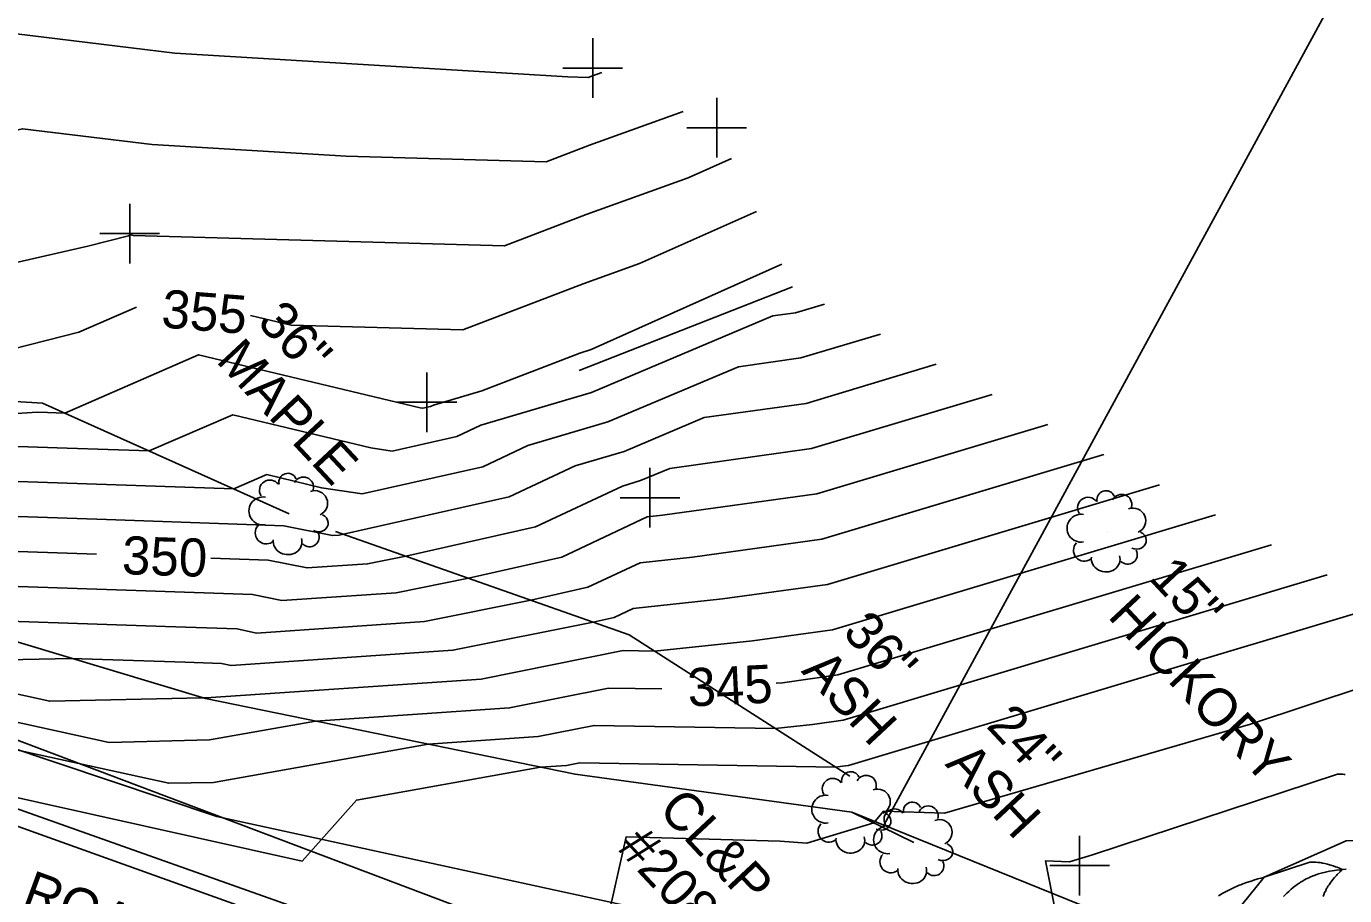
# Model space of a CAD drawing. Extents: x 487096 to 489566, y 221939 to 224454.
# Drawn here: x 488109.6 to 488220.2, y 223699.1 to 223772 of the extents above; entities that cross this region are included whole.
import ezdxf

# ---------------------------------------------------------------- set-up
doc = ezdxf.new("R2010")
doc.units = 0
for name, color, linetype in [('SV_BKLN_EARTH_TOP', 7, 'Continuous'), ('SV_FENC_FENCES', 7, 'Continuous'), ('SV_ROAD_BITRD', 7, 'Continuous'), ('SV_ROWL_HWYLOC', 7, 'Continuous'), ('SV_ROWL_PROP', 7, 'Continuous'), ('SV_ROWL_ROWL_TX', 7, 'Continuous'), ('SV_SURF_INDEX_CONTOUR', 7, 'Continuous'), ('SV_SURF_INTER_CONTOUR', 7, 'Continuous'), ('SV_SURF_SPOT', 7, 'Continuous'), ('SV_TRAF_PVMTL', 7, 'Continuous'), ('SV_TREE_TREELN', 7, 'Continuous'), ('SV_TREE_TREEVEG', 7, 'Continuous'), ('SV_TREE_TREEVEG_TX', 7, 'Continuous'), ('SV_UTOH_OVERHEAD_LINES', 7, 'Continuous'), ('SV_UTOH_UTOH_TX', 7, 'Continuous'), ('SV_WALL_STONE_WALL', 7, 'Continuous'), ('SV_WATR_INWETF', 7, 'Continuous'), ('SV_WATR_STREAM', 7, 'Continuous')]:
    doc.layers.add(name, color=color, linetype=linetype)

msp = doc.modelspace()

# ---------------------------------------------------------------- linework, layer by layer
at = {"layer": 'SV_BKLN_EARTH_TOP'}
for points in [[(488041.14, 223750.63), (488051.84, 223755.29), (488071.96, 223735.45), (488100.92, 223722.74), (488124.66, 223715.6), (488155.68, 223709.25)], [(488156.02, 223743.16), (488173.91, 223750.18)]]:
    msp.add_lwpolyline(points, dxfattribs=at)
at = {"layer": 'SV_FENC_FENCES'}
msp.add_lwpolyline([(487982.51, 223759.36), (488009.69, 223754.74), (488041.14, 223750.63), (488071.96, 223735.45), (488100.92, 223722.74), (488124.66, 223715.6), (488155.68, 223709.25), (488178.9, 223706.07), (488184.09, 223703.51)], dxfattribs=at)
at = {"layer": 'SV_ROAD_BITRD'}
msp.add_lwpolyline([(488195.32, 223676.23), (488156.88, 223689.32), (488086.86, 223714.16), (488030.43, 223734.89), (488029.27, 223735.37), (487991.62, 223750.14), (487935.77, 223771.81)], dxfattribs=at)
at = {"layer": 'SV_ROWL_HWYLOC'}
msp.add_lwpolyline([(487756.92, 223854.03), (487819.74, 223823.93), (487982.51, 223759.36), (488009.69, 223754.74), (488041.14, 223750.63), (488071.96, 223735.45), (488100.92, 223722.74), (488124.66, 223715.6), (488155.68, 223709.25), (488178.9, 223706.07), (488296.16, 223658.56), (488379.4, 223617.17), (488410.15, 223595.68), (488443.8, 223549.21), (488472.24, 223469.86), (488477.06, 223418.16), (488475.62, 223352.08), (488474.08, 223317.48), (488463.17, 223231.25), (488461.58, 223189.46)], dxfattribs=at)
at = {"layer": 'SV_ROWL_PROP'}
msp.add_line((488181.59, 223704.98), (488227.81, 223790.02), dxfattribs=at)
at = {"layer": 'SV_SURF_INDEX_CONTOUR'}
for points in [[(488128.45, 223747.77), (488131.84, 223746.96), (488146.26, 223746.56), (488156.35, 223750.41), (488161.09, 223752.12), (488170.9, 223756.5)], [(488037.34, 223752.77), (488037.74, 223752.37), (488038.25, 223751.01), (488040.43, 223749.72), (488040.51, 223749.7), (488041.1, 223749.58), (488048.91, 223750.37), (488064.4, 223742.91), (488076.16, 223740.46), (488080.11, 223740.49), (488094.61, 223741.41), (488114.05, 223746.37), (488118.87, 223748.47)], [(488032.68, 223745.08), (488035.52, 223743.4), (488036.1, 223743.22), (488040.76, 223742.28), (488044.31, 223742.64), (488058.56, 223735.77), (488076.6, 223728.82), (488077.44, 223728.86), (488090.01, 223727.53), (488095.27, 223727.56), (488103.98, 223728.12), (488115.53, 223727.73)], [(488125.12, 223727.4), (488129.92, 223727.23), (488133.19, 223726.57), (488138.26, 223726.91), (488141.48, 223727.56), (488152.35, 223730.01), (488159.66, 223733.45), (488161.16, 223733.9), (488163.62, 223734.93), (488175.5, 223736.59), (488190.66, 223741.14)], [(488214.09, 223728.51), (488177.73, 223717.59), (488173.08, 223716.94), (488172.55, 223716.89)], [(488162.96, 223716.42), (488158.49, 223716.49), (488150.18, 223714.82), (488133.89, 223713.71), (488124.99, 223712.13), (488116.59, 223711.93), (488092.03, 223717.31), (488085.77, 223718.14), (488084.12, 223718.08), (488077.99, 223720.44)], [(488218.43, 223698.98), (488218.52, 223699.22), (488218.53, 223699.23), (488218.58, 223699.37), (488218.62, 223699.42), (488218.72, 223699.66), (488218.76, 223699.71), (488218.8, 223699.76), (488218.84, 223699.86), (488218.93, 223699.96), (488219.02, 223700.12), (488219.07, 223700.18), (488219.19, 223700.32), (488219.26, 223700.43), (488219.4, 223700.59), (488219.44, 223700.64), (488219.55, 223700.76), (488219.6, 223700.83), (488219.85, 223701.07), (488219.86, 223701.09), (488220.02, 223701.23), (488220.02, 223701.23), (488220.04, 223701.26), (488220.02, 223701.26), (488219.87, 223701.33), (488219.6, 223701.44), (488219.46, 223701.49), (488219.27, 223701.56), (488219.07, 223701.62), (488218.98, 223701.65), (488218.79, 223701.7), (488218.7, 223701.73), (488218.57, 223701.76), (488218.39, 223701.8), (488218.3, 223701.81), (488218.18, 223701.83), (488217.99, 223701.85), (488217.82, 223701.87), (488217.74, 223701.87), (488217.62, 223701.87), (488217.51, 223701.87), (488217.45, 223701.87), (488217.33, 223701.86), (488213.5, 223700.6), (488213.38, 223700.57), (488213.21, 223700.52), (488212.95, 223700.46), (488212.79, 223700.41), (488212.68, 223700.38), (488212.47, 223700.31), (488212.31, 223700.26), (488212, 223700.16), (488211.71, 223700.05), (488211.52, 223699.98), (488211.4, 223699.93), (488211.16, 223699.82), (488211.02, 223699.76), (488210.76, 223699.64), (488210.51, 223699.52), (488210.35, 223699.43), (488210.24, 223699.38), (488210.03, 223699.26), (488209.8, 223699.13), (488209.65, 223699.04)]]:
    msp.add_lwpolyline(points, dxfattribs=at)
at = {"layer": 'SV_SURF_INTER_CONTOUR'}
for points in [[(487924.69, 223852.33), (487977.96, 223831.88), (487978.79, 223831), (487981.69, 223830.6), (487983.88, 223829.55), (488033.44, 223796.8), (488033.51, 223796.69), (488033.55, 223796.51), (488045.78, 223756.98), (488046.69, 223753.05), (488050.75, 223753.46), (488056.51, 223750.69), (488064.5, 223749.03), (488079.62, 223756.68), (488109.3, 223763.45), (488120.18, 223762.12), (488136.47, 223761.14), (488153.26, 223760.68), (488156.87, 223762.06), (488164.73, 223764.89)], [(487925.08, 223846.87), (487972.43, 223828.69), (487974.22, 223826.8), (487980.52, 223825.94), (487985.26, 223823.65), (488029.19, 223794.62), (488030.01, 223793.27), (488030.55, 223791.08), (488040.65, 223758.4), (488042.35, 223751.16), (488049.83, 223751.92), (488060.45, 223746.8), (488075.2, 223743.73), (488078.17, 223745.23), (488114.8, 223753.59), (488118.21, 223754.46), (488118.37, 223754.53), (488118.61, 223754.47), (488149.76, 223753.62), (488156.61, 223756.24), (488165.17, 223759.32), (488168.79, 223760.94)], [(488157.93, 223768.17), (488157.13, 223767.88), (488156.77, 223767.74), (488155.06, 223767.79), (488122.09, 223769.78), (488100.08, 223772.47), (488081.07, 223768.13), (488053.8, 223754.32), (488052.56, 223754.58), (488051.67, 223755.01), (488051.04, 223754.94), (488050.9, 223755.55), (488048.82, 223762.28), (488050.68, 223794.13), (487990.14, 223831.22)], [(488218.77, 223725.98), (488178.17, 223713.79), (488175.6, 223713.43), (488172.46, 223713.1), (488157.27, 223713.35), (488152.57, 223712.41), (488143.34, 223711.77), (488125.33, 223708.57), (488121.59, 223708.49), (488089.19, 223715.58), (488086.37, 223715.95), (488085.63, 223715.93), (488072.54, 223720.97), (488032.36, 223735.14), (488030.82, 223735.46), (488029.62, 223735.82), (488027.6, 223737.02), (488024.43, 223738.33), (487992.98, 223750.21), (487991.95, 223751.33), (487987.72, 223754.08), (487959.79, 223762.49)], [(488173.01, 223752.07), (488157.01, 223744.92), (488156.08, 223744.59), (488147.86, 223741.45), (488143.79, 223740.24), (488143.54, 223740.13), (488142.89, 223739.98), (488142.67, 223740.02), (488124.09, 223744.47), (488112.86, 223739.57), (488111.42, 223739.62), (488110.56, 223739.65), (488083.14, 223737.9)], [(488176.6, 223748.73), (488174.16, 223748), (488172.26, 223747.73), (488157.05, 223741.3), (488147.76, 223738.55), (488145.74, 223737.6), (488140.34, 223736.38), (488138.53, 223736.66), (488126.95, 223739.44), (488119.95, 223736.39), (488113.07, 223736.63), (488108.92, 223736.77)], [(488107.27, 223733.88), (488114.72, 223733.63), (488127.04, 223733.2), (488129.81, 223734.41), (488134.39, 223733.31), (488137.8, 223732.78), (488147.94, 223735.07), (488151.72, 223736.85), (488158.42, 223738.83), (488169.38, 223743.46), (488174.61, 223744.2), (488181.29, 223746.2)], [(488185.97, 223743.67), (488175.06, 223740.39), (488166.5, 223739.2), (488159.79, 223736.36), (488155.69, 223735.15), (488150.15, 223732.54), (488136.24, 223729.4), (488135.88, 223729.33), (488135.31, 223729.29), (488131.23, 223730.12), (488116.37, 223730.64), (488105.63, 223731)], [(488102.34, 223725.23), (488119.67, 223724.65), (488128.61, 223724.34), (488131.07, 223723.84), (488140.65, 223724.49), (488146.72, 223725.71), (488154.55, 223727.48), (488161.71, 223730.85), (488163.02, 223730.99), (488175.95, 223732.79), (488195.34, 223738.62)], [(488200.03, 223736.09), (488176.39, 223728.99), (488165.53, 223727.48), (488161.13, 223727.01), (488156.75, 223724.95), (488151.96, 223723.87), (488143.03, 223722.08), (488128.95, 223721.11), (488127.31, 223721.45), (488121.32, 223721.66), (488102.42, 223722.29)], [(488204.71, 223733.56), (488176.84, 223725.19), (488168.05, 223723.97), (488160.56, 223723.18), (488158.95, 223722.42), (488157.19, 223722.03), (488145.42, 223719.66), (488126.83, 223718.39), (488126, 223718.56), (488122.97, 223718.66), (488113.41, 223718.98), (488106.6, 223718.83)], [(488209.4, 223731.03), (488177.28, 223721.39), (488170.57, 223720.45), (488162.35, 223719.59), (488159.71, 223719.63), (488147.8, 223717.24), (488124.71, 223715.66), (488124.69, 223715.67), (488124.62, 223715.67), (488124.4, 223715.68), (488111.6, 223715.38), (488094.86, 223719.04)], [(488223.46, 223723.45), (488178.62, 223709.99), (488178.12, 223709.92), (488177.51, 223709.86), (488156.06, 223710.21), (488154.95, 223709.99), (488152.78, 223709.84), (488137.33, 223707.09), (488132.77, 223701.96), (488101.76, 223708.87)], [(488221.97, 223716.64), (488212.33, 223713.46), (488186.67, 223705.99), (488181.54, 223706.15), (488180.73, 223705.16), (488175.11, 223703.46), (488172.88, 223703.64), (488159.96, 223704.01), (488158.36, 223696.9), (488158.3, 223691.66), (488159.24, 223691.37), (488180.42, 223681.3), (488180.55, 223680.64), (488182.51, 223678.74), (488182.68, 223675.18), (488212.07, 223664.63), (488242.33, 223657.26)], [(488220.28, 223709.22), (488220.2, 223709.23), (488220.08, 223709.25), (488219.97, 223709.25), (488219.92, 223709.26), (488219.84, 223709.26), (488219.76, 223709.25), (488219.73, 223709.25), (488219.65, 223709.25), (488199.08, 223702.48), (488197.15, 223701.91), (488195.14, 223701.98), (488197.11, 223691.98)]]:
    msp.add_lwpolyline(points, dxfattribs=at)
at = {"layer": 'SV_SURF_SPOT'}
for p, q in [((488157.16, 223766.04), (488157.16, 223771.04)), ((488154.66, 223768.54), (488159.66, 223768.54)), ((488157.16, 223768.54), (488157.16, 223768.54)), ((488167.56, 223761.03), (488167.56, 223766.03)), ((488165.05, 223763.53), (488170.06, 223763.53)), ((488167.56, 223763.53), (488167.56, 223763.53)), ((488118.31, 223752.14), (488118.31, 223757.14)), ((488115.81, 223754.64), (488120.81, 223754.64)), ((488118.31, 223754.64), (488118.31, 223754.64)), ((488143.24, 223737.98), (488143.24, 223742.98)), ((488140.74, 223740.48), (488145.74, 223740.48)), ((488143.24, 223740.48), (488143.24, 223740.48)), ((488161.95, 223729.97), (488161.95, 223734.97)), ((488159.45, 223732.47), (488164.45, 223732.47)), ((488161.95, 223732.47), (488161.95, 223732.47)), ((488198, 223699.08), (488198, 223704.08)), ((488195.5, 223701.58), (488200.5, 223701.58)), ((488198, 223701.58), (488198, 223701.58))]:
    msp.add_line(p, q, dxfattribs=at)
at = {"layer": 'SV_TRAF_PVMTL'}
msp.add_lwpolyline([(488242.49, 223657.77), (488197.68, 223673.45), (488156.59, 223687.78), (488086.23, 223713.02)], dxfattribs=at)
at = {"layer": 'SV_TREE_TREELN'}
msp.add_lwpolyline([(487982.51, 223759.36), (488004.13, 223750.78), (488040.48, 223736.21), (488085.49, 223719.17), (488125.61, 223705.71), (488165.7, 223696.97), (488203.95, 223688.95)], dxfattribs=at)
at = {"layer": 'SV_TREE_TREEVEG'}
for p, q in [((488131.68, 223731.12), (488131.68, 223731.12)), ((488200.32, 223729.66), (488200.32, 223729.66)), ((488178.9, 223706.07), (488178.9, 223706.07)), ((488184.09, 223703.51), (488184.09, 223703.51))]:
    msp.add_line(p, q, dxfattribs=at)
for centre, radius, start, end in [((488130.07, 223733.08), 0.874, 35.9933, 211.459), ((488131.57, 223733.77), 0.75, 23.2911, 192.3579), ((488132.89, 223733.35), 0.85, 345.5308, 152.7093), ((488133.85, 223732), 1.06, 294.1859, 111.1082), ((488200.21, 223732.31), 0.75, 23.2911, 192.3579), ((488201.53, 223731.9), 0.85, 345.5308, 152.7093), ((488129.48, 223731.36), 1.17, 79.3292, 279.9889), ((488198.71, 223731.63), 0.874, 35.9933, 211.459), ((488202.49, 223730.54), 1.06, 294.1859, 111.1082), ((488198.12, 223729.91), 1.17, 79.3292, 279.9889), ((488129.76, 223729.51), 0.922, 137.0157, 304.5501), ((488198.41, 223728.06), 0.922, 137.0157, 304.5501), ((488178.79, 223708.72), 0.75, 23.2911, 192.3579), ((488177.29, 223708.03), 0.874, 35.9933, 211.459), ((488180.1, 223708.31), 0.85, 345.5308, 152.7093), ((488176.7, 223706.32), 1.17, 79.3292, 279.9889), ((488181.06, 223706.95), 1.06, 294.1859, 111.1082), ((488182.47, 223705.47), 0.874, 35.9933, 211.459), ((488183.97, 223706.16), 0.75, 23.2911, 192.3579), ((488185.29, 223705.74), 0.85, 345.5308, 152.7093), ((488176.98, 223704.47), 0.922, 137.0157, 304.5501), ((488186.25, 223704.39), 1.06, 294.1859, 111.1082), ((488181.89, 223703.75), 1.17, 79.3292, 279.9889), ((488182.17, 223701.9), 0.922, 137.0157, 304.5501)]:
    msp.add_arc(centre, radius, start, end, dxfattribs=at)
for centre, major_axis, ratio, start_param, end_param in [((488134.14, 223730.35), (0.822, -0.013), 0.901056, 4.216583, 7.444153), ((488133.4, 223729.15), (0.08, -0.798), 0.999752, 5.391582, 8.241319), ((488202.78, 223728.89), (0.822, -0.013), 0.901056, 4.216583, 7.444153), ((488131.55, 223728.78), (-1.2, 0.16), 0.902156, 0, 3.5401), ((488200.19, 223727.33), (-1.2, 0.16), 0.902156, 0, 3.5401), ((488202.04, 223727.69), (0.08, -0.798), 0.999752, 5.391582, 8.241319), ((488181.35, 223705.3), (0.822, -0.013), 0.901056, 4.216583, 7.444153), ((488178.77, 223703.73), (-1.2, 0.16), 0.902156, 0, 3.5401), ((488180.62, 223704.1), (0.08, -0.798), 0.999752, 5.391582, 8.241319), ((488186.54, 223702.74), (0.822, -0.013), 0.901056, 4.216583, 7.444153), ((488185.81, 223701.54), (0.08, -0.798), 0.999752, 5.391582, 8.241319), ((488183.96, 223701.17), (-1.2, 0.16), 0.902156, 0, 3.5401)]:
    msp.add_ellipse(centre, major_axis=major_axis, ratio=ratio, start_param=start_param, end_param=end_param, dxfattribs=at)
at = {"layer": 'SV_UTOH_OVERHEAD_LINES'}
msp.add_lwpolyline([(488477.01, 222631.44), (488424.13, 222778.25), (488391.68, 223012.96), (488449.87, 223205.72), (488470, 223438.33), (488349.56, 223622.89), (488159.18, 223693.12), (487993.17, 223755.78), (487804.2, 223830.22), (487742.26, 223860.21)], dxfattribs=at)
at = {"layer": 'SV_WALL_STONE_WALL'}
for points in [[(487884.38, 223823.97), (487906, 223824.38), (487928.22, 223803.19), (487939.33, 223794.64), (487970.27, 223785.24), (487995.99, 223777.6), (488005.6, 223769.42), (488016.25, 223765.18), (488051.84, 223755.29), (488077.81, 223742.44), (488110.99, 223740.41), (488131.68, 223731.12)], [(488135.58, 223729.64), (488160.22, 223720.96), (488178.72, 223709.08)]]:
    msp.add_lwpolyline(points, dxfattribs=at)
at = {"layer": 'SV_WATR_INWETF'}
msp.add_lwpolyline([(488239.84, 223704.58), (488220.38, 223703.66), (488213.5, 223700.6), (488197.29, 223680.56)], dxfattribs=at)
at = {"layer": 'SV_WATR_STREAM'}
msp.add_lwpolyline([(488220.37, 223701.28), (488220.02, 223701.25), (488219.85, 223701.24), (488219.55, 223701.2), (488219.4, 223701.18), (488219.18, 223701.14), (488218.96, 223701.11), (488218.85, 223701.08), (488218.63, 223701.04), (488218.53, 223701.01), (488218.37, 223700.97), (488218.16, 223700.91), (488218.06, 223700.88), (488217.9, 223700.83), (488217.67, 223700.75), (488217.47, 223700.67), (488217.38, 223700.63), (488217.23, 223700.56), (488217.09, 223700.49), (488217.01, 223700.46), (488216.87, 223700.38), (488216.8, 223700.34), (488216.7, 223700.28), (488216.54, 223700.19), (488216.44, 223700.12), (488216.37, 223700.07), (488216.24, 223699.98), (488216.14, 223699.91), (488215.95, 223699.76), (488215.76, 223699.6), (488215.63, 223699.49), (488215.55, 223699.41), (488215.38, 223699.26), (488215.29, 223699.17), (488215.11, 223698.98)], dxfattribs=at)

# ---------------------------------------------------------------- texts
at = {"layer": 'SV_ROWL_ROWL_TX'}
msp.add_text('CT ROUTE 188 - QUAKER FARMS ROAD', height=3.2, rotation=339.923, dxfattribs=at).set_placement((488043.92, 223722.06))
at = {"layer": 'SV_SURF_INDEX_CONTOUR'}
for s, rotation, p in [('355', 355.5228, (488120.9, 223746.77)), ('350', 358.0142, (488117.62, 223726.06)), ('345', 2.7896, (488165.18, 223714.93))]:
    msp.add_text(s, height=3.2, rotation=rotation, dxfattribs=at).set_placement(p)
at = {"layer": 'SV_TREE_TREEVEG_TX'}
for s, p in [('36"', (488128.91, 223747.13)), ('MAPLE', (488125.47, 223743.92)), ('15"', (488203.72, 223725.68)), ('HICKORY', (488200.28, 223722.47)), ('36"', (488178.02, 223721.08)), ('ASH', (488174.58, 223717.87)), ('24"', (488190.09, 223713.26)), ('ASH', (488186.65, 223710.05))]:
    msp.add_text(s, height=3.2, rotation=313.0386, dxfattribs=at).set_placement(p)
at = {"layer": 'SV_UTOH_UTOH_TX'}
for s, p in [('CL&P', (488162.56, 223706.19)), ('#20833', (488159.13, 223702.98))]:
    msp.add_text(s, height=3.2, rotation=313.0386, dxfattribs=at).set_placement(p)

doc.saveas('drawing.dxf')
